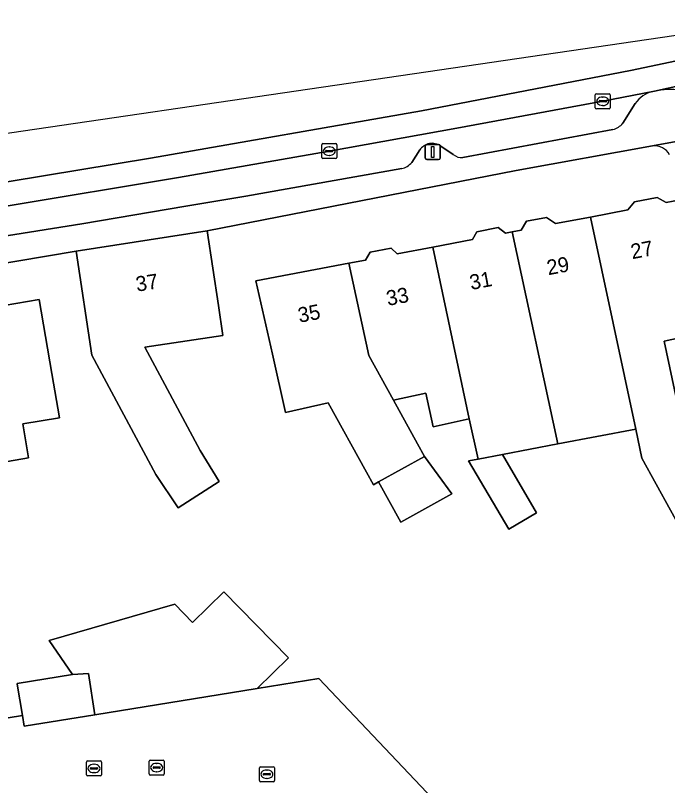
# Model space of a CAD drawing. Extents: x 159053 to 160042, y 380449 to 381423.
# Drawn here: x 159510.3 to 159553.7, y 381270.9 to 381322.1 of the extents above; entities that cross this region are included whole.
import ezdxf

# ---------------------------------------------------------------- set-up
doc = ezdxf.new("R2010")
doc.units = 0
for name, color, linetype in [('IMGEO_Erf', 7, 'Continuous'), ('IMGEO_Kolk', 7, 'Continuous'), ('IMGEO_Lichtmast', 7, 'Continuous'), ('IMGEO_Pand', 7, 'Continuous'), ('IMGEO_Pand_nummerreeks', 7, 'Continuous'), ('IMGEO_Parkeervlak_open', 7, 'Continuous'), ('IMGEO_Rijbaan_lokaal_gesloten', 7, 'Continuous'), ('IMGEO_Rijbaan_lokaal_open', 7, 'Continuous'), ('IMGEO_Rioolput', 7, 'Continuous'), ('IMGEO_Voetpad_open', 7, 'Continuous')]:
    doc.layers.add(name, color=color, linetype=linetype)

msp = doc.modelspace()

# ---------------------------------------------------------------- linework, layer by layer
at = {"layer": 'IMGEO_Erf'}
for points in [[(159552.705, 381313.429), (159543.626, 381311.785), (159523.095, 381307.767), (159523.841, 381302.802), (159524.139, 381300.817), (159518.944, 381300.036), (159522.619, 381293.167), (159523.897, 381291.098), (159521.161, 381289.363), (159519.673, 381291.562), (159515.422, 381299.507), (159514.383, 381306.418), (159504.373, 381304.731), (159504.45, 381304.533), (159500, 381303.852), (159485.55, 381301.639)], [(159554.858, 381287.461), (159552, 381292.661), (159551.59, 381294.585), (159546.401, 381293.601), (159542.723, 381292.903), (159544.997, 381289.018), (159543.138, 381287.93), (159540.477, 381292.477), (159541.1, 381292.595), (159540.502, 381295.272), (159538.122, 381294.753), (159537.634, 381296.991), (159535.475, 381296.521), (159537.086, 381293.612), (159537.55, 381292.775), (159539.369, 381290.288), (159535.975, 381288.408), (159534.494, 381291.083), (159534.154, 381290.894), (159533.69, 381291.731), (159531.138, 381296.339), (159528.297, 381295.701), (159527.428, 381299.565), (159526.332, 381304.443), (159532.513, 381305.625), (159533.614, 381305.835), (159533.921, 381306.346), (159535.332, 381306.616), (159535.721, 381306.238), (159538.088, 381306.69), (159540.728, 381307.195), (159541.027, 381307.718), (159542.446, 381307.989), (159542.936, 381307.617), (159543.368, 381307.7), (159543.975, 381307.816), (159544.313, 381308.41), (159545.647, 381308.665), (159546.254, 381308.252), (159548.568, 381308.694), (159551.052, 381309.169), (159551.498, 381309.705), (159553.011, 381309.994), (159553.604, 381309.656), (159554.534, 381309.834)], [(159504.914, 381302.005), (159511.926, 381303.217), (159512.769, 381298.289), (159513.272, 381295.351), (159510.835, 381294.941), (159511.217, 381292.673), (159508.407, 381292.2)], [(159507.252, 381274.976), (159510.808, 381275.554), (159510.47, 381277.631), (159510.463, 381277.675), (159514.139, 381278.272), (159512.58, 381280.544), (159520.937, 381282.943), (159522.118, 381281.737), (159524.197, 381283.771), (159528.49, 381279.384), (159526.41, 381277.349), (159530.524, 381278.017), (159538.088, 381270.011)]]:
    msp.add_lwpolyline(points, dxfattribs=at)
msp.add_lwpolyline([(159558.221, 381301.446), (159556.421, 381301.077), (159553.469, 381300.442), (159556.077, 381288.227), (159555.061, 381287.589), (159554.858, 381287.461), (159555.51, 381286.274), (159555.846, 381285.457), (159556.236, 381285.612), (159557.155, 381285.978), (159562.096, 381287.943), (159561.565, 381289.914)], close=True, dxfattribs=at)
msp.add_arc((159552.827, 381312.293), 1.143, 28.0919, 96.1322, dxfattribs=at)
at = {"layer": 'IMGEO_Kolk'}
for p, q in [((159548.893, 381315.963), (159548.893, 381316.815)), ((159548.968, 381316.889), (159549.82, 381316.889)), ((159549.381, 381316.669), (159549.406, 381316.669)), ((159549.894, 381316.815), (159549.894, 381315.963)), ((159549.152, 381316.383), (159549.152, 381316.395)), ((159549.59, 381316.346), (159549.192, 381316.346)), ((159549.195, 381316.432), (159549.593, 381316.432)), ((159549.404, 381316.109), (159549.379, 381316.109)), ((159549.636, 381316.395), (159549.636, 381316.383)), ((159549.82, 381315.889), (159548.968, 381315.889)), ((159530.783, 381313.574), (159531.635, 381313.574)), ((159530.708, 381312.648), (159530.708, 381313.5)), ((159530.967, 381313.068), (159530.967, 381313.08)), ((159531.405, 381313.031), (159531.007, 381313.031)), ((159531.01, 381313.117), (159531.408, 381313.117)), ((159531.196, 381313.354), (159531.221, 381313.354)), ((159531.451, 381313.08), (159531.451, 381313.068)), ((159531.709, 381313.5), (159531.709, 381312.648)), ((159531.635, 381312.574), (159530.783, 381312.574)), ((159531.219, 381312.794), (159531.194, 381312.794)), ((159515.068, 381271.603), (159515.068, 381272.455)), ((159515.143, 381272.529), (159515.995, 381272.529)), ((159515.37, 381272.072), (159515.768, 381272.072)), ((159515.556, 381272.309), (159515.581, 381272.309)), ((159516.069, 381272.455), (159516.069, 381271.603)), ((159526.561, 381271.217), (159526.561, 381272.069)), ((159526.636, 381272.143), (159527.488, 381272.143)), ((159527.562, 381272.069), (159527.562, 381271.217)), ((159515.995, 381271.529), (159515.143, 381271.529)), ((159515.327, 381272.023), (159515.327, 381272.035)), ((159515.765, 381271.986), (159515.367, 381271.986)), ((159515.579, 381271.749), (159515.554, 381271.749)), ((159515.811, 381272.035), (159515.811, 381272.023)), ((159526.82, 381271.637), (159526.82, 381271.649)), ((159527.258, 381271.6), (159526.86, 381271.6)), ((159526.863, 381271.686), (159527.261, 381271.686)), ((159527.049, 381271.923), (159527.074, 381271.923)), ((159527.304, 381271.649), (159527.304, 381271.637)), ((159527.488, 381271.143), (159526.636, 381271.143)), ((159527.072, 381271.363), (159527.047, 381271.363))]:
    msp.add_line(p, q, dxfattribs=at)
for points in [[(159548.893, 381315.963), (159548.893, 381316.815)], [(159548.968, 381316.889), (159549.82, 381316.889)], [(159549.894, 381316.815), (159549.894, 381315.963)], [(159549.82, 381315.889), (159548.968, 381315.889)], [(159530.783, 381313.574), (159531.635, 381313.574)], [(159530.708, 381312.648), (159530.708, 381313.5)], [(159531.709, 381313.5), (159531.709, 381312.648)], [(159531.635, 381312.574), (159530.783, 381312.574)], [(159515.068, 381271.603), (159515.068, 381272.455)], [(159515.143, 381272.529), (159515.995, 381272.529)], [(159516.069, 381272.455), (159516.069, 381271.603)], [(159526.561, 381271.217), (159526.561, 381272.069)], [(159526.636, 381272.143), (159527.488, 381272.143)], [(159527.562, 381272.069), (159527.562, 381271.217)], [(159515.995, 381271.529), (159515.143, 381271.529)], [(159527.488, 381271.143), (159526.636, 381271.143)]]:
    msp.add_lwpolyline(points, dxfattribs=at)
for centre, radius, start, end in [((159548.97, 381316.813), 0.0765, 91.552, 178.448), ((159548.97, 381316.813), 0.0765, 91.552, 178.448), ((159549.818, 381316.813), 0.0765, 1.552, 88.448), ((159549.818, 381316.813), 0.0765, 1.552, 88.448), ((159549.192, 381316.392), 0.0403, 85.8775, 175.7526), ((159549.189, 381316.382), 0.0366, 178.938, 274.7102), ((159549.593, 381316.389), 0.043, 264.8664, 352.4533), ((159549.597, 381316.394), 0.0386, 1.7309, 96.639), ((159548.97, 381315.965), 0.0765, 181.552, 268.448), ((159548.97, 381315.965), 0.0765, 181.552, 268.448), ((159549.818, 381315.965), 0.0765, 271.552, 358.448), ((159549.818, 381315.965), 0.0765, 271.552, 358.448), ((159530.785, 381313.498), 0.0765, 91.552, 178.448), ((159530.785, 381313.498), 0.0765, 91.552, 178.448), ((159531.633, 381313.498), 0.0765, 1.552, 88.448), ((159531.633, 381313.498), 0.0765, 1.552, 88.448), ((159531.007, 381313.077), 0.0403, 85.8775, 175.7526), ((159531.004, 381313.067), 0.0366, 178.938, 274.7102), ((159531.408, 381313.074), 0.043, 264.8664, 352.4533), ((159531.412, 381313.079), 0.0386, 1.7309, 96.639), ((159530.785, 381312.65), 0.0765, 181.552, 268.448), ((159530.785, 381312.65), 0.0765, 181.552, 268.448), ((159531.633, 381312.65), 0.0765, 271.552, 358.448), ((159531.633, 381312.65), 0.0765, 271.552, 358.448), ((159515.145, 381272.453), 0.0765, 91.552, 178.448), ((159515.145, 381272.453), 0.0765, 91.552, 178.448), ((159515.367, 381272.032), 0.0403, 85.8775, 175.7526), ((159515.772, 381272.034), 0.0386, 1.7309, 96.639), ((159515.993, 381272.453), 0.0765, 1.552, 88.448), ((159515.993, 381272.453), 0.0765, 1.552, 88.448), ((159526.638, 381272.067), 0.0765, 91.552, 178.448), ((159526.638, 381272.067), 0.0765, 91.552, 178.448), ((159527.486, 381272.067), 0.0765, 1.552, 88.448), ((159527.486, 381272.067), 0.0765, 1.552, 88.448), ((159515.145, 381271.605), 0.0765, 181.552, 268.448), ((159515.145, 381271.605), 0.0765, 181.552, 268.448), ((159515.364, 381272.022), 0.0366, 178.938, 274.7102), ((159515.768, 381272.029), 0.043, 264.8664, 352.4533), ((159515.993, 381271.605), 0.0765, 271.552, 358.448), ((159515.993, 381271.605), 0.0765, 271.552, 358.448), ((159526.86, 381271.646), 0.0403, 85.8775, 175.7526), ((159526.857, 381271.636), 0.0366, 178.938, 274.7102), ((159527.261, 381271.643), 0.043, 264.8664, 352.4533), ((159527.265, 381271.648), 0.0386, 1.7309, 96.639), ((159526.638, 381271.219), 0.0765, 181.552, 268.448), ((159526.638, 381271.219), 0.0765, 181.552, 268.448), ((159527.486, 381271.219), 0.0765, 271.552, 358.448), ((159527.486, 381271.219), 0.0765, 271.552, 358.448)]:
    msp.add_arc(centre, radius, start, end, dxfattribs=at)
for centre, major_axis, ratio, start_param, end_param in [((159549.38, 381316.389), (-0.387, 0.002), 0.722429, 4.712389, 7.853982), ((159549.405, 381316.389), (-0.39, 0.002), 0.717154, 1.570796, 4.712389), ((159531.195, 381313.074), (-0.387, 0.002), 0.722429, 4.712389, 7.853982), ((159531.22, 381313.074), (-0.39, 0.002), 0.717154, 1.570796, 4.712389), ((159515.555, 381272.029), (-0.387, 0.002), 0.722429, 4.712389, 7.853982), ((159515.58, 381272.029), (-0.39, 0.002), 0.717154, 1.570796, 4.712389), ((159527.048, 381271.643), (-0.387, 0.002), 0.722429, 4.712389, 7.853982), ((159527.073, 381271.643), (-0.39, 0.002), 0.717154, 1.570796, 4.712389)]:
    msp.add_ellipse(centre, major_axis=major_axis, ratio=ratio, start_param=start_param, end_param=end_param, dxfattribs=at)
at = {"layer": 'IMGEO_Lichtmast'}
for p, q in [((159537.593, 381312.616), (159537.593, 381313.416)), ((159537.593, 381313.416), (159537.593, 381312.616)), ((159537.693, 381313.516), (159538.483, 381313.516)), ((159538.483, 381313.516), (159537.693, 381313.516)), ((159538.583, 381313.416), (159538.583, 381312.616)), ((159538.583, 381312.616), (159538.583, 381313.416)), ((159538.483, 381312.516), (159537.693, 381312.516)), ((159537.693, 381312.516), (159538.483, 381312.516))]:
    msp.add_line(p, q, dxfattribs=at)
msp.add_lwpolyline([(159538.013, 381313.391), (159538.163, 381313.391), (159538.163, 381312.641), (159538.013, 381312.641), (159538.013, 381313.391)], dxfattribs=at)
for centre, start, end in [((159537.693, 381313.416), 90, 180), ((159537.693, 381313.416), 90, 180), ((159538.483, 381313.416), 0, 90), ((159538.483, 381313.416), 360, 90), ((159537.693, 381312.616), 180, 270), ((159537.693, 381312.616), 180, 270), ((159538.483, 381312.616), 270, 0), ((159538.483, 381312.616), 270, 0)]:
    msp.add_arc(centre, 0.1, start, end, dxfattribs=at)
at = {"layer": 'IMGEO_Pand'}
for points in [[(159556.421, 381301.077), (159554.534, 381309.834), (159553.604, 381309.656), (159553.011, 381309.994), (159551.498, 381309.705), (159551.052, 381309.169), (159548.568, 381308.694), (159551.59, 381294.585), (159552, 381292.661), (159554.858, 381287.461), (159555.061, 381287.589), (159556.077, 381288.227), (159553.469, 381300.442)], [(159548.568, 381308.694), (159546.254, 381308.252), (159545.647, 381308.665), (159544.313, 381308.41), (159543.975, 381307.816), (159543.368, 381307.7), (159546.401, 381293.601), (159551.59, 381294.585)], [(159543.368, 381307.7), (159542.936, 381307.617), (159542.446, 381307.989), (159541.027, 381307.718), (159540.728, 381307.195), (159538.088, 381306.69), (159540.502, 381295.272), (159541.1, 381292.595), (159542.723, 381292.903), (159546.401, 381293.601)], [(159523.095, 381307.767), (159514.383, 381306.418), (159515.422, 381299.507), (159519.673, 381291.562), (159521.161, 381289.363), (159523.897, 381291.098), (159522.619, 381293.167), (159518.944, 381300.036), (159524.139, 381300.817), (159523.841, 381302.802)], [(159538.088, 381306.69), (159535.721, 381306.238), (159535.332, 381306.616), (159533.921, 381306.346), (159533.614, 381305.835), (159532.513, 381305.625), (159533.834, 381299.485), (159535.475, 381296.521), (159537.634, 381296.991), (159538.122, 381294.753), (159540.502, 381295.272)], [(159533.834, 381299.485), (159532.513, 381305.625), (159526.332, 381304.443), (159527.428, 381299.565), (159528.297, 381295.701), (159531.138, 381296.339), (159533.69, 381291.731), (159534.154, 381290.894), (159534.494, 381291.083), (159537.55, 381292.775), (159537.086, 381293.612), (159535.475, 381296.521)], [(159504.914, 381302.005), (159506.236, 381294.238), (159506.629, 381291.901), (159508.407, 381292.2), (159511.217, 381292.673), (159510.835, 381294.941), (159513.272, 381295.351), (159512.769, 381298.289), (159511.926, 381303.217)], [(159537.55, 381292.775), (159534.494, 381291.083), (159535.975, 381288.408), (159539.369, 381290.288)], [(159542.723, 381292.903), (159541.1, 381292.595), (159540.477, 381292.477), (159543.138, 381287.93), (159544.997, 381289.018)], [(159514.139, 381278.272), (159515.204, 381278.349), (159515.623, 381275.597), (159526.41, 381277.349), (159528.49, 381279.384), (159524.197, 381283.771), (159522.118, 381281.737), (159520.937, 381282.943), (159512.58, 381280.544)], [(159515.204, 381278.349), (159514.139, 381278.272), (159510.463, 381277.675), (159510.47, 381277.631), (159510.808, 381275.554), (159510.925, 381274.834), (159515.623, 381275.597)]]:
    msp.add_lwpolyline(points, close=True, dxfattribs=at)
at = {"layer": 'IMGEO_Parkeervlak_open'}
for points in [[(159552.716, 381317.04), (159549.389, 381316.39), (159539.699, 381314.595), (159531.204, 381313.075), (159521.192, 381311.328), (159509.718, 381309.412), (159500, 381307.878), (159490.742, 381306.485), (159486.58, 381305.853)], [(159550.72, 381314.93), (159551.555, 381316.238)], [(159540.095, 381312.656), (159550.071, 381314.52)], [(159536.694, 381312.315), (159537.224, 381313.15)], [(159538.618, 381313.407), (159539.456, 381312.859)], [(159489.945, 381304.382), (159500, 381305.941), (159509.315, 381307.385), (159514.749, 381308.232), (159521.67, 381309.407), (159525.666, 381310.076), (159536.032, 381311.918)]]:
    msp.add_lwpolyline(points, dxfattribs=at)
for centre, radius, start, end in [((159553.135, 381315.191), 1.896, 102.7837, 146.4885), ((159549.828, 381315.624), 1.131, 282.4357, 322.1288), ((159538.044, 381312.614), 0.979, 54.0792, 146.8125), ((159539.981, 381313.406), 0.758, 226.1412, 278.6104), ((159535.799, 381313.057), 1.162, 281.5602, 320.3419)]:
    msp.add_arc(centre, radius, start, end, dxfattribs=at)
at = {"layer": 'IMGEO_Rijbaan_lokaal_gesloten'}
msp.add_lwpolyline([(159485.73, 381310.724), (159485.73, 381310.724), (159486.249, 381307.229), (159498.232, 381309.125), (159519.334, 381312.605), (159537.334, 381315.754), (159551.245, 381318.435), (159564.404, 381321.209), (159579.772, 381324.783), (159593.307, 381328.356), (159605.338, 381331.789), (159626.628, 381338.418), (159649.891, 381345.846), (159673.107, 381353.416), (159685.932, 381357.579), (159685.204, 381359.893), (159670.766, 381354.293), (159597.865, 381331.733), (159554.111, 381320.745)], close=True, dxfattribs=at)
msp.add_lwpolyline([(159564.404, 381321.209), (159551.245, 381318.435), (159537.334, 381315.754), (159519.334, 381312.605), (159498.232, 381309.125), (159486.249, 381307.229), (159486.456, 381305.834), (159486.58, 381305.853), (159490.742, 381306.485), (159500, 381307.878), (159509.718, 381309.412), (159521.192, 381311.328), (159531.204, 381313.075), (159539.699, 381314.595), (159549.389, 381316.39), (159552.716, 381317.04), (159552.829, 381317.062), (159570.995, 381321.057)], dxfattribs=at)
at = {"layer": 'IMGEO_Rijbaan_lokaal_open'}
for points in [[(159570.995, 381321.057), (159552.829, 381317.062)], [(159538.088, 381270.011), (159530.524, 381278.017), (159526.41, 381277.349), (159515.623, 381275.597), (159510.925, 381274.834), (159510.808, 381275.554), (159507.252, 381274.976), (159504.186, 381274.353), (159504.187, 381274.222), (159501.223, 381273.823), (159501.233, 381273.658), (159500.381, 381273.53), (159496.356, 381272.925), (159496.334, 381273.061), (159488.814, 381271.948), (159488.87, 381271.571), (159489.62, 381266.493)]]:
    msp.add_lwpolyline(points, dxfattribs=at)
msp.add_arc((159553.938, 381311.476), 5.695, 32.3671, 101.2311, dxfattribs=at)
at = {"layer": 'IMGEO_Rioolput'}
for p, q in [((159519.31, 381272.585), (159520.162, 381272.585)), ((159519.235, 381271.659), (159519.235, 381272.511)), ((159519.494, 381272.079), (159519.494, 381272.091)), ((159519.932, 381272.042), (159519.534, 381272.042)), ((159519.537, 381272.128), (159519.935, 381272.128)), ((159519.723, 381272.365), (159519.748, 381272.365)), ((159519.978, 381272.091), (159519.978, 381272.079)), ((159520.236, 381272.511), (159520.236, 381271.659)), ((159520.162, 381271.585), (159519.31, 381271.585)), ((159519.746, 381271.805), (159519.721, 381271.805))]:
    msp.add_line(p, q, dxfattribs=at)
for points in [[(159519.31, 381272.585), (159520.162, 381272.585)], [(159519.235, 381271.659), (159519.235, 381272.511)], [(159520.236, 381272.511), (159520.236, 381271.659)], [(159520.162, 381271.585), (159519.31, 381271.585)]]:
    msp.add_lwpolyline(points, dxfattribs=at)
for centre, radius, start, end in [((159519.312, 381272.509), 0.0765, 91.552, 178.448), ((159519.312, 381272.509), 0.0765, 91.552, 178.448), ((159520.16, 381272.509), 0.0765, 1.552, 88.448), ((159520.16, 381272.509), 0.0765, 1.552, 88.448), ((159519.534, 381272.088), 0.0403, 85.8775, 175.7526), ((159519.531, 381272.078), 0.0366, 178.938, 274.7102), ((159519.935, 381272.085), 0.043, 264.8664, 352.4533), ((159519.939, 381272.09), 0.0386, 1.7309, 96.639), ((159519.312, 381271.661), 0.0765, 181.552, 268.448), ((159519.312, 381271.661), 0.0765, 181.552, 268.448), ((159520.16, 381271.661), 0.0765, 271.552, 358.448), ((159520.16, 381271.661), 0.0765, 271.552, 358.448)]:
    msp.add_arc(centre, radius, start, end, dxfattribs=at)
for centre, major_axis, ratio, start_param, end_param in [((159519.722, 381272.085), (-0.387, 0.002), 0.722429, 4.712389, 7.853982), ((159519.747, 381272.085), (-0.39, 0.002), 0.717154, 1.570796, 4.712389)]:
    msp.add_ellipse(centre, major_axis=major_axis, ratio=ratio, start_param=start_param, end_param=end_param, dxfattribs=at)
at = {"layer": 'IMGEO_Voetpad_open'}
for points in [[(159552.829, 381317.062), (159552.716, 381317.04)], [(159551.555, 381316.238), (159550.72, 381314.93)], [(159485.55, 381301.639), (159500, 381303.852), (159504.45, 381304.533), (159504.373, 381304.731), (159514.383, 381306.418), (159523.095, 381307.767), (159543.626, 381311.785), (159552.705, 381313.429), (159558.748, 381314.525)], [(159550.071, 381314.52), (159540.095, 381312.656)], [(159558.748, 381314.525), (159552.705, 381313.429)], [(159537.224, 381313.15), (159536.694, 381312.315)], [(159539.456, 381312.859), (159538.618, 381313.407)], [(159536.032, 381311.918), (159525.666, 381310.076), (159521.67, 381309.407), (159514.749, 381308.232), (159509.315, 381307.385), (159500, 381305.941), (159489.945, 381304.382)]]:
    msp.add_lwpolyline(points, dxfattribs=at)
for centre, radius, start, end in [((159553.938, 381311.476), 5.695, 32.3671, 101.2311), ((159553.135, 381315.191), 1.896, 102.7837, 146.4885), ((159549.828, 381315.624), 1.131, 282.4357, 322.1288), ((159538.044, 381312.614), 0.979, 54.0792, 146.8125), ((159552.827, 381312.293), 1.143, 28.0919, 96.1322), ((159539.981, 381313.406), 0.758, 226.1412, 278.6104), ((159535.799, 381313.057), 1.162, 281.5602, 320.3419)]:
    msp.add_arc(centre, radius, start, end, dxfattribs=at)

# ---------------------------------------------------------------- texts
at = {"layer": 'IMGEO_Pand_nummerreeks'}
for s, rotation, p in [('27', 10.8232, (159551.355, 381305.886)), ('29', 10.8232, (159545.772, 381304.819)), ('37', 8.8006, (159518.424, 381303.724)), ('31', 10.8232, (159540.642, 381303.838)), ('33', 10.8232, (159535.104, 381302.78)), ('35', 10.8232, (159529.226, 381301.656))]:
    msp.add_text(s, height=1, rotation=rotation, dxfattribs=at).set_placement(p)

doc.saveas('drawing.dxf')
